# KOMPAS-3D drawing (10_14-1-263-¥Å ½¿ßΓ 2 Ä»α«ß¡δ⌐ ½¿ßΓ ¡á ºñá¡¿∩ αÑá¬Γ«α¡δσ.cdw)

Views: Вид 1
Referenced files: Опросный лист на ОПУ.cdw
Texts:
  Текст на чертеже
  Размерные надписи
  Шероховатость
  Линия-выноска #1
  Линия-выноска #2
  Линия-выноска #3
  Отклонения формы и база
  Заголовок таблицы
  Ячейка таблицы
  Стрелка вида
  Обозначение изменения
  Фигурная скобка
  Номер узла
  Марка координационной оси
  VRCB
  Выносная надпись
  Обозначение узла
  Марка/позиционное обозначение с линией-выноской
  Марка/позиционное обозначение на линии
  Марка/позиционное обозначение без линии-выноски
  Normal
  txt
  Simplex
  Txt
  Body Text
  heading 1
  Знак Знак Знак Знак Знак Знак
  Verdana
  Лит-Масса-Масштаб
  Материал-Предприятие
  Additional DXF text style 0
  Обычный
  Термин
  Список определений
  Адрес
  Цитаты
  Форматированный
  Courier New
  Z-конец формы
  Z-начало формы
  Title Specification
  Body Specification ( left align )
  Body Specificaton ( centered )
  Без имени
  heading 8
  heading 3
  heading 6
  heading 7
  ТекстШаг1
  russ
  ООббыыччнныыйй
  ТТееррммиинн
  ССппииссоокк ооппррееддееллеенниийй
  ААддрреесс
  ЦЦииттааттыы
  ФФооррммааттиирроовваанннныыйй
  Z-ккооннеецц ффооррммыы
  Z-ннааччааллоо ффооррммыы
  heading 2
  heading 4
  heading 5
  heading 9
  Абзац Знак
  MS Sans Serif
  ГОСТ_МНЕ
  ESK - Обозначение
  Подпись в квадратике
  цепи
  Денис
  GOST 2.304 type A
  rustxt
  ссылки
  текст переноса
  табл
  Тексты. 3,2
  ЗОНА_привяз
  Body Text 3
  Title
  Маркировка
  клеммы, контакты
  тексты табл
  AGOpus
  footer
  TXT
  NormalParagraphStyle
  Definition Term
  Definition List
  Address
  Blockquote
  Preformatted
  z-Bottom of Form
  z-Top of Form
  header
  Заказ №:
  Покупатель:
  ОАО «Тюменьэнерго» Северные электрические сети
  Место установки здания:
  Тюменская область, Ямало-Ненецкий
  автономный округ, г. Новый Уренгой
  ПС Опорная 110 кВ
  Планировка здания:
  10/14-1-263-ЭП (лист 3, 4)
  Количество блоков:
  2 Наличие в модульном эдании:
  - освещения
  естественное, рабочее (см. 10/14-1-263-ЭП, лист 5,6)
  - тип ламп освещения
  светодиодные
  - отопления
  - вентиляции
  - система организованного слива
  - степень огнестойкости здания
  - категория по пожарной безопасности
  - кровля
  - материал стен и потолка
  - высота фундамента (мм)
  естественная,приточно-вытяжная (см. 10/14-1-263-ЭП, лист 5,6)
  односкатная
  сендвич-панель
  свайный фундамент (см. прилагаемые документы
  - климатическое исполнение
  ХЛ1 (ГОСТ 15150-69)
  - сейсмичность (балл)
  4 Дополнительная информация
  5 Дополнительная комплектация
  В комплект поставки включить оборудование
  в соответствии с 10/14-1-263-ЭП, лист 3-8.
  каркасное, быстровозводимое
  Таблица 2
  № договора
  Согласовал
  Подпись
  Дата
  Заказчик, адрес, индекс             Согласовано
  Руководитель предприятия
  Подпись, дата
  Заказчик и его адрес
  Таблица 1
  Филиал ОАО «Тюменьэнерго» Северные электрические
  сети Тюменская область, Ямало-Ненецкий
  Согласовано
  Директор филиала ОАО «Тюменьэнерго» Северные электрические
  сети
  Фамилия                  Подпись
  CONTINUOUS_RGB_0_0_0_THICK_0.18
  POLYLINE_STYLE_0.40_RGB_0_0_0
  POLYLINE_STYLE_0.18_RGB_0_0_0
  POLYLINE_STYLE_0.50_RGB_0_0_0
  Реконструкция ПС 110 кВ Опорная
  (замена трансформаторов 16МВА на 40МВА)
  Схема пневматическая структурная
  Опросный лист на изготовление
  здания реакторной модульного типа
  реакторных модульного типа
  Разраб.
  Скахин
Dimensions and other numbers on the sheet: 10/14-1-263-ЭП; 7; 3,2_; 1,8; 2.5 курсив; 2,5; 3,5; 3,2 (надписи); 3,2; 3.5; 2.5; 2,5_3; 3,5_01; 2,5_01; 3,5_tabl; 5_заголовок; 2,3_; 3,2_зона не привяз; 2,5 грязносинь; 2,5 (контакты, клеммы); 5; 3,2 элементы; 3,2 линия; 3,2 таблица; 3.2 маркировка; 2.5_Э5_надписи; 2.5_Э5_ссылки; 2.5_кабель; 3.2; 2.5 надписи; 3,2 (Зоны); 5,0_белый_подчёркнутый; 2; 10/14-1-113-КС, лист 11); 3 Климатические условия; 1 Тип здания; 04.08/64.002-ЭП1-; 11.12; 4; 6; 8; 9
